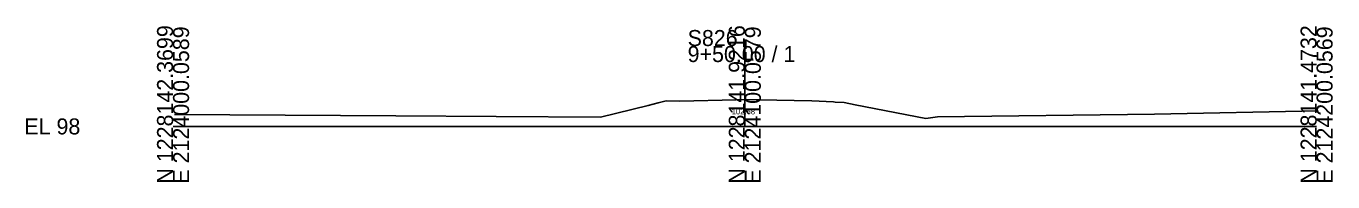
# Model space of a CAD drawing. Extents: x 2118382 to 2118616, y 1213030 to 1222057.
# Drawn here: x 2118381.9 to 2118610.4, y 1220030.1 to 1220057.3 of the extents above; entities that cross this region are included whole.
import ezdxf

# ---------------------------------------------------------------- set-up
doc = ezdxf.new("R2010")
doc.units = 0
for name, color, linetype in [('XS_CELL', 7, 'Continuous'), ('XS_X_GROUND', 7, 'Continuous'), ('XS_X_GROUND_TX', 7, 'Continuous')]:
    doc.layers.add(name, color=color, linetype=linetype)

msp = doc.modelspace()

# ---------------------------------------------------------------- linework, layer by layer
at = {"layer": 'XS_CELL'}
for p, q in [((2118507.6, 1220039.8), (2118507.6, 1220053.85)), ((2118407.6, 1220039.8), (2118507.6, 1220039.8)), ((2118507.6, 1220039.8), (2118607.6, 1220039.8))]:
    msp.add_line(p, q, dxfattribs=at)
at = {"layer": 'XS_X_GROUND'}
for p, q in [((2118492.47, 1220043.91), (2118493.87, 1220044.26)), ((2118493.87, 1220044.26), (2118496.25, 1220044.22)), ((2118496.25, 1220044.22), (2118506.11, 1220044.45)), ((2118506.11, 1220044.45), (2118507.6, 1220044.48)), ((2118507.6, 1220044.48), (2118509.62, 1220044.45)), ((2118509.62, 1220044.45), (2118510.11, 1220044.44)), ((2118510.11, 1220044.44), (2118519.31, 1220044.28)), ((2118519.31, 1220044.28), (2118523.09, 1220044.08)), ((2118407.87, 1220041.9), (2118446.58, 1220041.63)), ((2118482.34, 1220041.42), (2118490.69, 1220043.47)), ((2118490.69, 1220043.47), (2118492.47, 1220043.91)), ((2118523.09, 1220044.08), (2118523.41, 1220044.06)), ((2118523.41, 1220044.06), (2118524.96, 1220043.98)), ((2118524.96, 1220043.98), (2118526.9, 1220043.59)), ((2118526.9, 1220043.59), (2118539.28, 1220041.16)), ((2118541.31, 1220041.45), (2118579.25, 1220041.93)), ((2118579.25, 1220041.93), (2118607.87, 1220042.5)), ((2118446.58, 1220041.63), (2118464.13, 1220041.52)), ((2118464.13, 1220041.52), (2118482.34, 1220041.42)), ((2118539.28, 1220041.16), (2118541.31, 1220041.45))]:
    msp.add_line(p, q, dxfattribs=at)

# ---------------------------------------------------------------- texts
at = {"layer": 'XS_CELL'}
for s, p in [('N 1228142.3699', (2118407.6, 1220029.8)), ('E 2124000.0589', (2118410.4, 1220029.8)), ('N 1228141.9216', (2118507.6, 1220029.8)), ('E 2124100.0579', (2118510.4, 1220029.8)), ('N 1228141.4732', (2118607.6, 1220029.8)), ('E 2124200.0569', (2118610.4, 1220029.8))]:
    msp.add_text(s, height=2.8, rotation=90, dxfattribs=at).set_placement(p)
for s, p in [('S826', (2118497.6, 1220053.85)), ('9+50.00 / 1', (2118497.6, 1220051.05)), ('EL 98', (2118381.6, 1220038.4))]:
    msp.add_text(s, height=2.8, dxfattribs=at).set_placement(p)
at = {"layer": 'XS_X_GROUND_TX'}
msp.add_text('102.68', height=1, dxfattribs=at).set_placement((2118505.3, 1220041.91))

doc.saveas('drawing.dxf')
